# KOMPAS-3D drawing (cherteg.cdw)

Views: Вид контроля
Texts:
  Экологические проблемы при производстве шунгизита
  КР-2068029.280202.024.010
  asus
  kontora
  Поз.
  Храние сырьевых материалов
  Дозировка сырья
  Очистка воздуха от пыли
  Обжиг
  Охлаждение
  Промежуточное хранение готовой продукции
  Подача готовой продукции
  Транспортировка готовой продукции
  Промежуточное хранение гтовой продукции
  Сортировка
  Газоудаление
  Обоз.
  Контроль запыленности,  1...6 мг/м 3
  Контроль вибрации:
  - частота,  15 Гц
  - амплитуда,  0,003...0,6 мм
  Контроль шума, 60 дБ
  Контроль освещенности,  5000 лк
  Контроль микроклимата рабочей зоны:
  -температурный градиент t, 20  5  0 С
  - влажность w, 60...70%
  Экологический контроль
  Экспликация
  POLYLINE_STYLE_0.35_RGB_179_179_179
  POLYLINE_STYLE_0.20_RGB_179_179_179
  POLYLINE_STYLE_0.90_RGB_179_179_179
  Экологические проблемы при
  производстве шунгизита
  Экологические проблемы при-
  Технологическая схема
  производства шунгизита
  Разраб.
  Чемисова А.Н
  Пров.
  Васюнина С.В
  БГИТА
  Н.контр.
Dimensions and other numbers on the sheet: 1; 2; 3; 4; 5; 6; 7; 8; 9; 10; 11; 1:1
